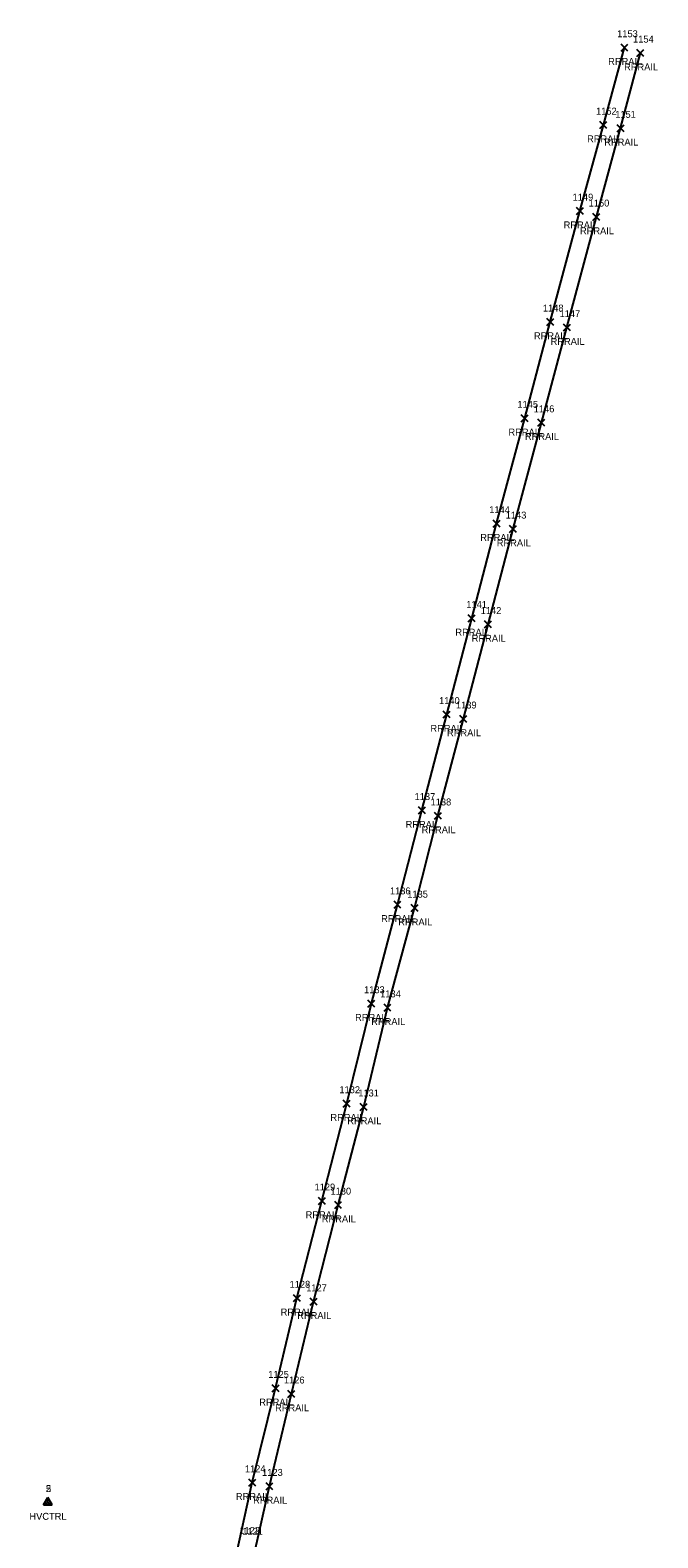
# Model space of a CAD drawing. Extents: x 1715662 to 1717487, y 887396 to 890004.
# Drawn here: x 1716490 to 1716670.9, y 888704 to 889138.8 of the extents above; entities that cross this region are included whole.
import ezdxf

# ---------------------------------------------------------------- set-up
doc = ezdxf.new("R2010")
doc.units = 0
for name, color, linetype in [('C_A', 7, 'Continuous'), ('C_I', 7, 'Continuous'), ('CPSM', 7, 'Continuous'), ('R_A', 7, 'Continuous'), ('R_I', 7, 'Continuous'), ('R_TIC', 7, 'Continuous'), ('RR', 7, 'Continuous')]:
    doc.layers.add(name, color=color, linetype=linetype)

msp = doc.modelspace()

# ---------------------------------------------------------------- linework, layer by layer
at = {"layer": 'CPSM'}
for p, q in [((1716493.86, 888713.49), (1716495.11, 888715.65)), ((1716493.86, 888713.49), (1716495.11, 888715.65)), ((1716493.86, 888713.49), (1716495.11, 888715.65)), ((1716493.86, 888713.49), (1716495.11, 888715.65)), ((1716493.86, 888713.49), (1716495.11, 888715.65)), ((1716493.86, 888713.49), (1716495.11, 888715.65)), ((1716493.86, 888713.49), (1716495.11, 888715.65)), ((1716493.88, 888713.49), (1716495.13, 888715.66)), ((1716496.36, 888713.49), (1716495.11, 888715.65)), ((1716495.11, 888714.21), (1716495.11, 888715.65)), ((1716496.36, 888713.49), (1716495.11, 888715.65)), ((1716495.11, 888714.21), (1716495.11, 888715.65)), ((1716496.36, 888713.49), (1716495.11, 888715.65)), ((1716495.11, 888714.21), (1716495.11, 888715.65)), ((1716496.36, 888713.49), (1716495.11, 888715.65)), ((1716495.11, 888714.21), (1716495.11, 888715.65)), ((1716496.36, 888713.49), (1716495.11, 888715.65)), ((1716495.11, 888714.21), (1716495.11, 888715.65)), ((1716496.36, 888713.49), (1716495.11, 888715.65)), ((1716495.11, 888714.21), (1716495.11, 888715.65)), ((1716496.36, 888713.49), (1716495.11, 888715.65)), ((1716495.11, 888714.21), (1716495.11, 888715.65)), ((1716496.38, 888713.49), (1716495.13, 888715.66)), ((1716495.13, 888714.21), (1716495.13, 888715.66)), ((1716493.86, 888713.49), (1716495.11, 888714.21)), ((1716493.86, 888713.49), (1716495.11, 888714.21)), ((1716493.86, 888713.49), (1716495.11, 888714.21)), ((1716493.86, 888713.49), (1716495.11, 888714.21)), ((1716493.86, 888713.49), (1716495.11, 888714.21)), ((1716493.86, 888713.49), (1716495.11, 888714.21)), ((1716493.86, 888713.49), (1716495.11, 888714.21)), ((1716493.86, 888713.49), (1716496.36, 888713.49)), ((1716493.86, 888713.49), (1716496.36, 888713.49)), ((1716493.86, 888713.49), (1716496.36, 888713.49)), ((1716493.86, 888713.49), (1716496.36, 888713.49)), ((1716493.86, 888713.49), (1716496.36, 888713.49)), ((1716493.86, 888713.49), (1716496.36, 888713.49)), ((1716493.86, 888713.49), (1716496.36, 888713.49)), ((1716493.88, 888713.49), (1716495.13, 888714.21)), ((1716493.88, 888713.49), (1716496.38, 888713.49)), ((1716495.11, 888714.21), (1716495.11, 888714.21)), ((1716495.11, 888714.21), (1716496.36, 888713.49)), ((1716495.11, 888714.21), (1716495.11, 888714.21)), ((1716495.11, 888714.21), (1716496.36, 888713.49)), ((1716495.11, 888714.21), (1716495.11, 888714.21)), ((1716495.11, 888714.21), (1716496.36, 888713.49)), ((1716495.11, 888714.21), (1716495.11, 888714.21)), ((1716495.11, 888714.21), (1716496.36, 888713.49)), ((1716495.11, 888714.21), (1716495.11, 888714.21)), ((1716495.11, 888714.21), (1716496.36, 888713.49)), ((1716495.11, 888714.21), (1716495.11, 888714.21)), ((1716495.11, 888714.21), (1716496.36, 888713.49)), ((1716495.11, 888714.21), (1716495.11, 888714.21)), ((1716495.11, 888714.21), (1716496.36, 888713.49)), ((1716495.13, 888714.21), (1716495.13, 888714.21)), ((1716495.13, 888714.21), (1716496.38, 888713.49))]:
    msp.add_line(p, q, dxfattribs=at)
at = {"layer": 'R_TIC'}
for points in [[(1716660.3, 889132.77), (1716662.3, 889134.77)], [(1716662.3, 889132.77), (1716660.3, 889134.77)], [(1716664.89, 889131.22), (1716666.89, 889133.22)], [(1716666.89, 889131.22), (1716664.89, 889133.22)], [(1716654.22, 889110.45), (1716656.22, 889112.45)], [(1716656.22, 889110.45), (1716654.22, 889112.45)], [(1716659.17, 889109.52), (1716661.17, 889111.52)], [(1716661.17, 889109.52), (1716659.17, 889111.52)], [(1716647.47, 889085.64), (1716649.47, 889087.64)], [(1716649.47, 889085.64), (1716647.47, 889087.64)], [(1716652.18, 889083.94), (1716654.18, 889085.94)], [(1716654.18, 889083.94), (1716652.18, 889085.94)], [(1716638.91, 889053.66), (1716640.91, 889055.66)], [(1716640.91, 889053.66), (1716638.91, 889055.66)], [(1716643.7, 889052.05), (1716645.7, 889054.05)], [(1716645.7, 889052.05), (1716643.7, 889054.05)], [(1716631.56, 889025.89), (1716633.56, 889027.89)], [(1716633.56, 889025.89), (1716631.56, 889027.89)], [(1716636.33, 889024.6), (1716638.33, 889026.6)], [(1716638.33, 889024.6), (1716636.33, 889026.6)], [(1716623.43, 888995.51), (1716625.43, 888997.51)], [(1716625.43, 888995.51), (1716623.43, 888997.51)], [(1716628.19, 888993.95), (1716630.19, 888995.95)], [(1716630.19, 888993.95), (1716628.19, 888995.95)], [(1716616.27, 888968.18), (1716618.27, 888970.18)], [(1716618.27, 888968.18), (1716616.27, 888970.18)], [(1716620.98, 888966.43), (1716622.98, 888968.43)], [(1716622.98, 888966.43), (1716620.98, 888968.43)], [(1716609.07, 888940.45), (1716611.07, 888942.45)], [(1716611.07, 888940.45), (1716609.07, 888942.45)], [(1716613.87, 888939.18), (1716615.87, 888941.18)], [(1716615.87, 888939.18), (1716613.87, 888941.18)], [(1716601.93, 888912.78), (1716603.93, 888914.78)], [(1716603.93, 888912.78), (1716601.93, 888914.78)], [(1716606.54, 888911.22), (1716608.54, 888913.22)], [(1716608.54, 888911.22), (1716606.54, 888913.22)], [(1716594.88, 888885.58), (1716596.88, 888887.58)], [(1716596.88, 888885.58), (1716594.88, 888887.58)], [(1716599.82, 888884.62), (1716601.82, 888886.62)], [(1716601.82, 888884.62), (1716599.82, 888886.62)], [(1716587.36, 888857.08), (1716589.36, 888859.08)], [(1716589.36, 888857.08), (1716587.36, 888859.08)], [(1716592, 888855.88), (1716594, 888857.88)], [(1716594, 888855.88), (1716592, 888857.88)], [(1716580.24, 888828.24), (1716582.24, 888830.24)], [(1716582.24, 888828.24), (1716580.24, 888830.24)], [(1716585.13, 888827.29), (1716587.13, 888829.29)], [(1716587.13, 888827.29), (1716585.13, 888829.29)], [(1716573.11, 888800.18), (1716575.11, 888802.18)], [(1716575.11, 888800.18), (1716573.11, 888802.18)], [(1716577.78, 888798.99), (1716579.78, 888800.99)], [(1716579.78, 888798.99), (1716577.78, 888800.99)], [(1716565.9, 888772.12), (1716567.9, 888774.12)], [(1716567.9, 888772.12), (1716565.9, 888774.12)], [(1716570.69, 888771.11), (1716572.69, 888773.11)], [(1716572.69, 888771.11), (1716570.69, 888773.11)], [(1716559.75, 888746.15), (1716561.75, 888748.15)], [(1716561.75, 888746.15), (1716559.75, 888748.15)], [(1716564.31, 888744.52), (1716566.31, 888746.52)], [(1716566.31, 888744.52), (1716564.31, 888746.52)], [(1716553.01, 888718.92), (1716555.01, 888720.92)], [(1716555.01, 888718.92), (1716553.01, 888720.92)], [(1716557.99, 888717.88), (1716559.99, 888719.88)], [(1716559.99, 888717.88), (1716557.99, 888719.88)]]:
    msp.add_lwpolyline(points, dxfattribs=at)
at = {"layer": 'RR'}
for points in [[(1716548.86, 888696.72), (1716554.01, 888719.92), (1716560.75, 888747.15), (1716566.9, 888773.12), (1716574.11, 888801.18), (1716581.24, 888829.24), (1716588.36, 888858.08), (1716595.88, 888886.58), (1716602.93, 888913.78), (1716610.07, 888941.45), (1716617.27, 888969.18), (1716624.43, 888996.51), (1716632.56, 889026.89), (1716639.91, 889054.66), (1716648.47, 889086.64), (1716655.22, 889111.45), (1716661.3, 889133.77)], [(1716553.66, 888695.32), (1716558.99, 888718.88), (1716565.31, 888745.52), (1716571.69, 888772.11), (1716578.78, 888799.99), (1716586.13, 888828.29), (1716593, 888856.88), (1716600.82, 888885.62), (1716607.54, 888912.22), (1716614.87, 888940.18), (1716621.98, 888967.43), (1716629.19, 888994.95), (1716637.33, 889025.6), (1716644.7, 889053.05), (1716653.18, 889084.94), (1716660.17, 889110.52), (1716665.89, 889132.22)]]:
    msp.add_lwpolyline(points, dxfattribs=at)

# ---------------------------------------------------------------- texts
at = {"layer": 'C_A'}
for p in [(1716489.8, 888709.21), (1716489.8, 888709.21), (1716489.8, 888709.21), (1716489.8, 888709.21), (1716489.8, 888709.21), (1716489.8, 888709.21), (1716489.8, 888709.21), (1716489.82, 888709.21)]:
    msp.add_text('HVCTRL', height=2, dxfattribs=at).set_placement(p)
at = {"layer": 'C_I'}
for s, p in [('2', (1716494.54, 888717.21)), ('2', (1716494.54, 888717.21)), ('2', (1716494.54, 888717.21)), ('5', (1716494.56, 888717.21)), ('2', (1716494.54, 888717.21)), ('2', (1716494.54, 888717.21)), ('2', (1716494.54, 888717.21)), ('2', (1716494.54, 888717.21))]:
    msp.add_text(s, height=2, dxfattribs=at).set_placement(p)
at = {"layer": 'R_A'}
for p in [(1716656.59, 889128.77), (1716661.18, 889127.22), (1716650.51, 889106.45), (1716655.47, 889105.52), (1716643.76, 889081.64), (1716648.47, 889079.94), (1716635.2, 889049.66), (1716639.99, 889048.05), (1716627.85, 889021.89), (1716632.62, 889020.6), (1716619.72, 888991.51), (1716624.49, 888989.95), (1716612.56, 888964.18), (1716617.27, 888962.43), (1716605.36, 888936.45), (1716610.16, 888935.18), (1716598.22, 888908.78), (1716602.83, 888907.22), (1716591.17, 888881.58), (1716596.11, 888880.62), (1716583.66, 888853.08), (1716588.3, 888851.88), (1716576.54, 888824.24), (1716581.42, 888823.29), (1716569.4, 888796.18), (1716574.07, 888794.99), (1716562.2, 888768.12), (1716566.98, 888767.11), (1716556.04, 888742.15), (1716560.6, 888740.52), (1716549.3, 888714.92), (1716554.28, 888713.88)]:
    msp.add_text('RRRAIL', height=2, dxfattribs=at).set_placement(p)
at = {"layer": 'R_I'}
for s, p in [('1153', (1716659.18, 889136.77)), ('1154', (1716663.76, 889135.22)), ('1152', (1716653.09, 889114.45)), ('1151', (1716658.61, 889113.52)), ('1149', (1716646.34, 889089.64)), ('1150', (1716650.97, 889087.94)), ('1148', (1716637.78, 889057.66)), ('1147', (1716642.58, 889056.05)), ('1145', (1716630.43, 889029.89)), ('1146', (1716635.14, 889028.6)), ('1144', (1716622.31, 888999.51)), ('1143', (1716627.07, 888997.95)), ('1141', (1716615.71, 888972.18)), ('1142', (1716619.85, 888970.43)), ('1140', (1716607.86, 888944.45)), ('1139', (1716612.73, 888943.18)), ('1137', (1716600.8, 888916.78)), ('1138', (1716605.41, 888915.22)), ('1136', (1716593.7, 888889.58)), ('1135', (1716598.69, 888888.62)), ('1133', (1716586.24, 888861.08)), ('1134', (1716590.88, 888859.88)), ('1132', (1716579.12, 888832.24)), ('1131', (1716584.57, 888831.29)), ('1129', (1716571.97, 888804.18)), ('1130', (1716576.56, 888802.99)), ('1128', (1716564.78, 888776.12)), ('1127', (1716569.56, 888775.11)), ('1125', (1716558.62, 888750.15)), ('1126', (1716563.13, 888748.52)), ('1124', (1716551.89, 888722.92)), ('1123', (1716556.86, 888721.88)), ('1122', (1716550.29, 888705.12)), ('1121', (1716551.15, 888704.89))]:
    msp.add_text(s, height=2, dxfattribs=at).set_placement(p)

doc.saveas('drawing.dxf')
